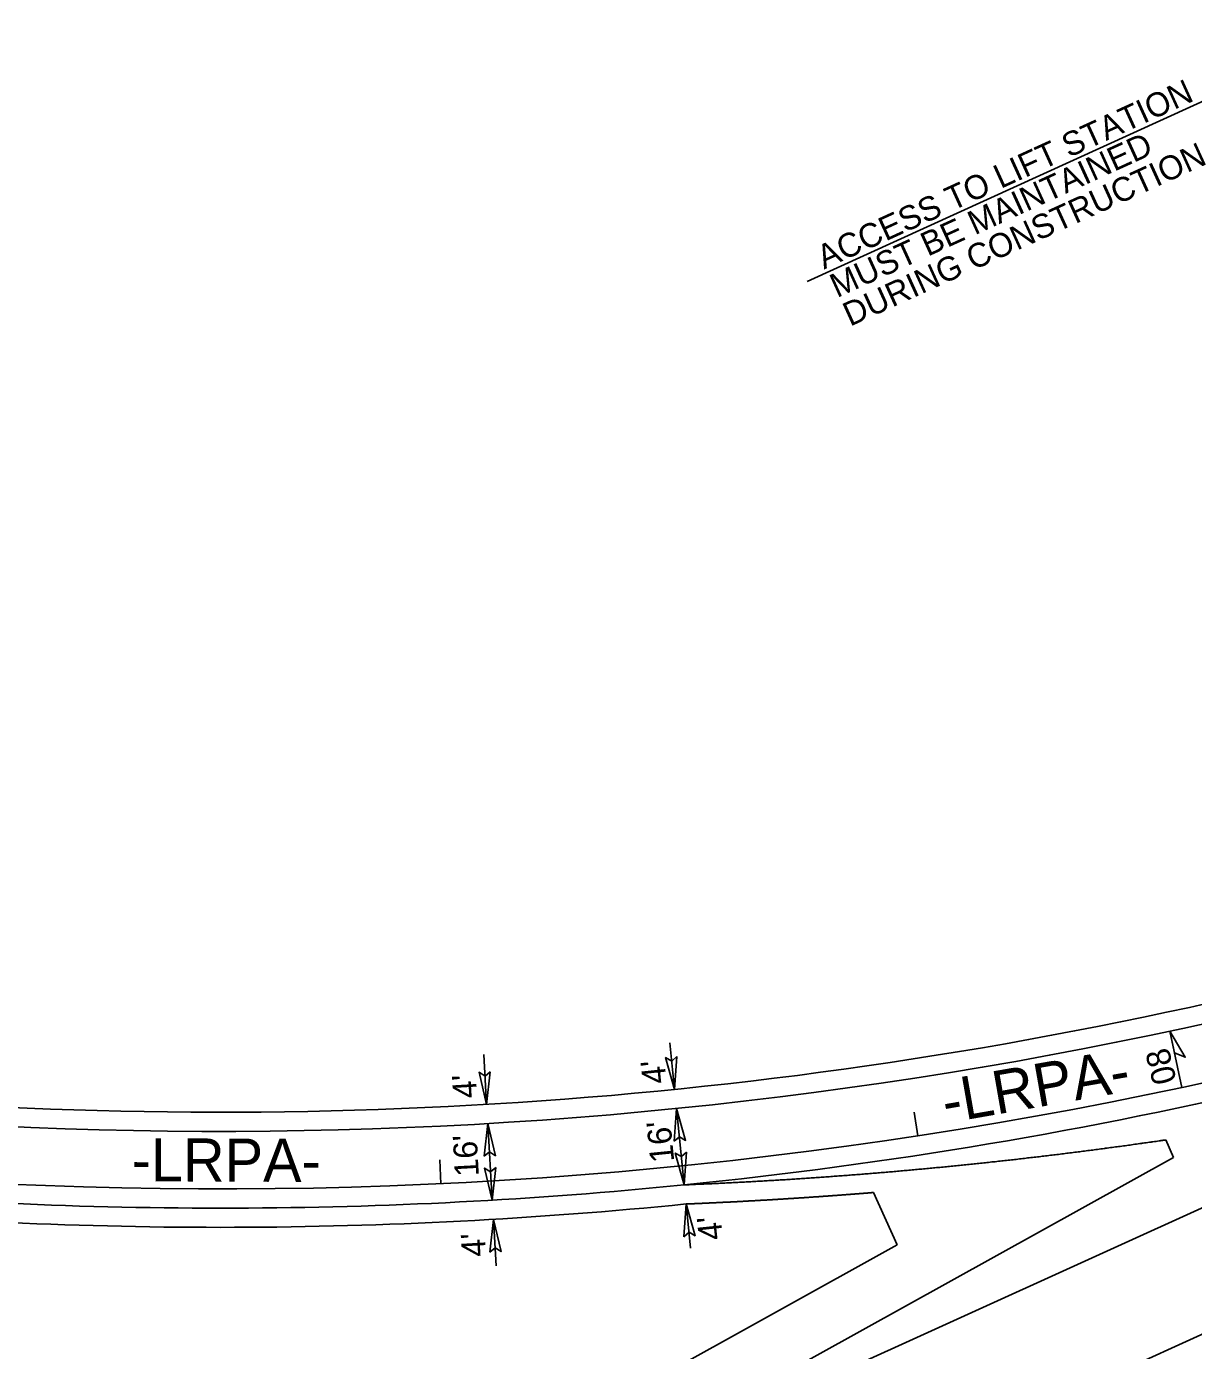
# Model space of a CAD drawing. Extents: x 2242984 to 2250974, y 661492 to 664681.
# Drawn here: x 2248196.5 to 2248439.9, y 663145.5 to 663421.5 of the extents above; entities that cross this region are included whole.
import ezdxf

# ---------------------------------------------------------------- set-up
doc = ezdxf.new("R2010")
doc.units = 0
for name, color, linetype in [('Prop Dimension', 7, 'Continuous'), ('Prop Dimension Text', 7, 'Continuous'), ('Prop DSN Text', 7, 'Continuous'), ('Prop EOT', 7, 'Continuous'), ('Prop Horizontal Alignment', 7, 'Continuous'), ('Prop Horizontal Alignment Curve and Spiral Data', 7, 'Continuous'), ('Prop Horizontal Alignment Tick Small', 7, 'Continuous'), ('Prop Lane Lines', 7, 'Continuous'), ('Prop Paved Shoulder', 7, 'Continuous'), ('Prop Superelevation  Arrow CELL', 7, 'Continuous'), ('Prop Superelevation Label', 7, 'Continuous'), ('Prop Terminator CELL', 7, 'Continuous'), ('Scratch_Level_2', 7, 'Continuous')]:
    doc.layers.add(name, color=color, linetype=linetype)

msp = doc.modelspace()

# ---------------------------------------------------------------- linework, layer by layer
at = {"layer": 'Prop Dimension'}
for p, q in [((2248330.69, 663209.61), (2248331.67, 663199.9)), ((2248292.46, 663196.78), (2248291.85, 663207.19)), ((2248332.07, 663195.92), (2248333.67, 663180)), ((2248293.64, 663176.81), (2248292.7, 663192.78)), ((2248335, 663166.83), (2248334.07, 663176.02)), ((2248294.45, 663163.1), (2248293.87, 663172.82))]:
    msp.add_line(p, q, dxfattribs=at)
at = {"layer": 'Prop DSN Text'}
msp.add_line((2248447.47, 663408.55), (2248359.33, 663368.39), dxfattribs=at)
at = {"layer": 'Prop EOT'}
for p, q in [((2248200.21, 663039.2), (2249433.89, 663599.6)), ((2248435.75, 663185.74), (2248434.1, 663189.38)), ((2248304.14, 663112.77), (2248435.75, 663185.74))]:
    msp.add_line(p, q, dxfattribs=at)
for radius, start, end in [(948, 264.58168, 292.13013), (964, 264.58443, 275.75472)]:
    msp.add_arc((2248237.01, 664139.15), radius, start, end, dxfattribs=at)
for points in [[(2248434.1, 663189.38), (2248433.42, 663189.28), (2248432.74, 663189.18), (2248432.07, 663189.08), (2248431.39, 663188.99), (2248430.71, 663188.89), (2248430.04, 663188.79), (2248429.36, 663188.7), (2248428.68, 663188.6), (2248428, 663188.51), (2248427.33, 663188.41), (2248426.65, 663188.32), (2248425.97, 663188.23), (2248425.3, 663188.13), (2248424.62, 663188.04), (2248423.94, 663187.95), (2248423.26, 663187.86), (2248422.59, 663187.77), (2248421.91, 663187.68), (2248421.23, 663187.58), (2248420.55, 663187.5), (2248419.88, 663187.41), (2248419.2, 663187.32), (2248418.52, 663187.23), (2248417.84, 663187.14), (2248417.17, 663187.05), (2248416.49, 663186.97), (2248415.81, 663186.88), (2248415.13, 663186.8), (2248414.46, 663186.71), (2248413.78, 663186.63), (2248413.1, 663186.54), (2248412.42, 663186.46), (2248411.74, 663186.37), (2248411.07, 663186.29), (2248410.39, 663186.21), (2248409.71, 663186.13), (2248409.03, 663186.05), (2248408.35, 663185.96), (2248407.68, 663185.88), (2248407, 663185.8), (2248406.32, 663185.72), (2248405.64, 663185.65), (2248404.96, 663185.57), (2248404.29, 663185.49), (2248403.61, 663185.41), (2248402.93, 663185.33), (2248402.25, 663185.26), (2248401.57, 663185.18), (2248400.89, 663185.11), (2248400.22, 663185.03), (2248399.54, 663184.96), (2248398.86, 663184.88), (2248398.18, 663184.81), (2248397.5, 663184.74), (2248396.82, 663184.66), (2248396.15, 663184.59), (2248395.47, 663184.52), (2248394.79, 663184.45), (2248394.11, 663184.38), (2248393.43, 663184.31), (2248392.75, 663184.24), (2248392.07, 663184.17), (2248391.4, 663184.1), (2248390.72, 663184.03), (2248390.04, 663183.96), (2248389.36, 663183.89), (2248388.68, 663183.83), (2248388, 663183.76), (2248387.32, 663183.69), (2248386.64, 663183.63), (2248385.97, 663183.56), (2248385.29, 663183.5), (2248384.61, 663183.44), (2248383.93, 663183.37)], [(2248383.93, 663183.37), (2248383.25, 663183.31), (2248382.57, 663183.25), (2248381.89, 663183.18), (2248381.21, 663183.12), (2248380.53, 663183.06), (2248379.86, 663183), (2248379.18, 663182.94), (2248378.5, 663182.88), (2248377.82, 663182.82), (2248377.14, 663182.76), (2248376.46, 663182.7), (2248375.78, 663182.65), (2248375.1, 663182.59), (2248374.42, 663182.53), (2248373.74, 663182.48), (2248373.06, 663182.42), (2248372.39, 663182.37), (2248371.71, 663182.31), (2248371.03, 663182.26), (2248370.35, 663182.2), (2248369.67, 663182.15), (2248368.99, 663182.1), (2248368.31, 663182.04), (2248367.63, 663181.99), (2248366.95, 663181.94), (2248366.27, 663181.89), (2248365.59, 663181.84), (2248364.92, 663181.79), (2248364.24, 663181.74), (2248363.56, 663181.69), (2248362.88, 663181.64), (2248362.2, 663181.59), (2248361.52, 663181.54), (2248360.84, 663181.5), (2248360.16, 663181.45), (2248359.48, 663181.4), (2248358.8, 663181.36), (2248358.12, 663181.31), (2248357.44, 663181.27), (2248356.76, 663181.22), (2248356.09, 663181.18), (2248355.41, 663181.14), (2248354.73, 663181.09), (2248354.05, 663181.05), (2248353.37, 663181.01), (2248352.69, 663180.97), (2248352.01, 663180.93), (2248351.33, 663180.89), (2248350.65, 663180.85), (2248349.97, 663180.81), (2248349.29, 663180.77), (2248348.61, 663180.73), (2248347.93, 663180.69), (2248347.26, 663180.65), (2248346.58, 663180.62), (2248345.9, 663180.58), (2248345.22, 663180.54), (2248344.54, 663180.51), (2248343.86, 663180.47), (2248343.18, 663180.44), (2248342.5, 663180.41), (2248341.82, 663180.37), (2248341.14, 663180.34), (2248340.46, 663180.31), (2248339.78, 663180.27), (2248339.1, 663180.24), (2248338.43, 663180.21), (2248337.75, 663180.18), (2248337.07, 663180.15), (2248336.39, 663180.12), (2248335.71, 663180.09), (2248335.03, 663180.06), (2248333.67, 663180)]]:
    msp.add_spline(points, degree=3, dxfattribs=at)
at = {"layer": 'Prop Horizontal Alignment'}
msp.add_arc((2248237.01, 664139.15), 960, 261.59641, 292.13013, dxfattribs=at)
at = {"layer": 'Prop Horizontal Alignment Tick Small'}
for p, q in [((2248382.4, 663190.22), (2248381.64, 663195.16)), ((2248282.94, 663180.25), (2248282.71, 663185.24))]:
    msp.add_line(p, q, dxfattribs=at)
at = {"layer": 'Prop Lane Lines'}
msp.add_line((2248304.14, 663112.77), (2248668.27, 663278.18), dxfattribs=at)
msp.add_arc((2248237.01, 664139.15), 964, 275.75472, 290.97015, dxfattribs=at)
at = {"layer": 'Prop Paved Shoulder'}
for p, q in [((2248378.08, 663167.49), (2248373.12, 663178.41)), ((2248298.74, 663123.5), (2248378.08, 663167.49))]:
    msp.add_line(p, q, dxfattribs=at)
for radius, start, end in [(944, 264.58097, 283.54456), (968, 264.58516, 275.75472)]:
    msp.add_arc((2248237.01, 664139.15), radius, start, end, dxfattribs=at)
msp.add_open_spline([(2248373.12, 663178.41), (2248372.98, 663178.4), (2248372.85, 663178.39), (2248372.71, 663178.38), (2248372.48, 663178.36), (2248372.26, 663178.34), (2248372.03, 663178.32), (2248371.8, 663178.3), (2248371.57, 663178.29), (2248371.35, 663178.27), (2248371.12, 663178.25), (2248370.89, 663178.23), (2248370.66, 663178.21), (2248370.44, 663178.2), (2248370.21, 663178.18), (2248369.98, 663178.16), (2248369.75, 663178.14), (2248369.53, 663178.13), (2248369.3, 663178.11), (2248369.07, 663178.09), (2248368.85, 663178.07), (2248368.62, 663178.05), (2248368.39, 663178.04), (2248368.16, 663178.02), (2248367.94, 663178), (2248367.71, 663177.99), (2248367.48, 663177.97), (2248367.25, 663177.95), (2248367.03, 663177.93), (2248366.8, 663177.92), (2248366.57, 663177.9), (2248366.34, 663177.88), (2248366.12, 663177.87), (2248365.89, 663177.85), (2248365.66, 663177.83), (2248365.44, 663177.82), (2248365.21, 663177.8), (2248364.98, 663177.78), (2248364.75, 663177.77), (2248364.53, 663177.75), (2248364.3, 663177.73), (2248364.07, 663177.72), (2248363.84, 663177.7), (2248363.62, 663177.68), (2248363.39, 663177.67), (2248363.16, 663177.65), (2248362.93, 663177.63), (2248362.71, 663177.62), (2248362.48, 663177.6), (2248362.25, 663177.59), (2248362.03, 663177.57), (2248361.8, 663177.55), (2248361.57, 663177.54), (2248361.34, 663177.52), (2248361.12, 663177.51), (2248360.89, 663177.49), (2248360.66, 663177.48), (2248360.43, 663177.46), (2248360.21, 663177.44), (2248359.98, 663177.43), (2248359.75, 663177.41), (2248359.52, 663177.4), (2248359.3, 663177.38), (2248359.07, 663177.37), (2248358.84, 663177.35), (2248358.62, 663177.34), (2248358.39, 663177.32), (2248358.16, 663177.31), (2248357.93, 663177.29), (2248357.71, 663177.28), (2248357.48, 663177.26), (2248357.25, 663177.25), (2248357.02, 663177.23), (2248356.8, 663177.22), (2248356.57, 663177.2), (2248356.34, 663177.19), (2248356.11, 663177.17), (2248355.89, 663177.16), (2248355.66, 663177.15), (2248355.43, 663177.13), (2248355.2, 663177.12), (2248354.98, 663177.1), (2248354.75, 663177.09), (2248354.52, 663177.07), (2248354.3, 663177.06), (2248354.07, 663177.05), (2248353.84, 663177.03), (2248353.61, 663177.02), (2248353.39, 663177), (2248353.16, 663176.99), (2248352.93, 663176.98), (2248352.7, 663176.96), (2248352.48, 663176.95), (2248352.25, 663176.93), (2248352.02, 663176.92), (2248351.79, 663176.91), (2248351.57, 663176.89), (2248351.34, 663176.88), (2248351.11, 663176.87), (2248350.89, 663176.85), (2248350.66, 663176.84), (2248350.43, 663176.83), (2248350.2, 663176.81), (2248349.98, 663176.8), (2248349.75, 663176.79), (2248349.52, 663176.78), (2248349.29, 663176.76), (2248349.07, 663176.75), (2248348.84, 663176.74), (2248348.61, 663176.72), (2248348.38, 663176.71), (2248348.16, 663176.7), (2248347.93, 663176.69), (2248347.7, 663176.67), (2248347.47, 663176.66), (2248347.25, 663176.65), (2248347.02, 663176.64), (2248346.79, 663176.62), (2248346.57, 663176.61), (2248346.34, 663176.6), (2248346.11, 663176.59), (2248345.88, 663176.57), (2248345.66, 663176.56), (2248345.43, 663176.55), (2248345.2, 663176.54), (2248344.97, 663176.53), (2248344.75, 663176.51), (2248344.52, 663176.5), (2248344.29, 663176.49), (2248344.06, 663176.48), (2248343.84, 663176.47), (2248343.61, 663176.46), (2248343.38, 663176.44), (2248343.15, 663176.43), (2248342.93, 663176.42), (2248342.7, 663176.41), (2248342.47, 663176.4), (2248342.25, 663176.39), (2248342.02, 663176.38), (2248341.79, 663176.37), (2248341.56, 663176.35), (2248341.34, 663176.34), (2248341.11, 663176.33), (2248340.88, 663176.32), (2248340.65, 663176.31), (2248340.43, 663176.3), (2248340.2, 663176.29), (2248339.97, 663176.28), (2248339.74, 663176.27), (2248339.52, 663176.26), (2248339.29, 663176.25), (2248339.06, 663176.24), (2248338.84, 663176.22), (2248338.61, 663176.21), (2248338.38, 663176.2), (2248338.15, 663176.19), (2248337.93, 663176.18), (2248337.7, 663176.17), (2248337.47, 663176.16), (2248337.24, 663176.15), (2248337.02, 663176.14), (2248336.79, 663176.13), (2248336.56, 663176.12), (2248336.33, 663176.11), (2248336.11, 663176.1), (2248335.88, 663176.09), (2248335.65, 663176.08), (2248335.42, 663176.07), (2248335.2, 663176.06), (2248334.74, 663176.05), (2248334.29, 663176.03), (2248334.07, 663176.02)], degree=3, dxfattribs=at)
at = {"layer": 'Prop Superelevation  Arrow CELL'}
msp.add_line((2248434.97, 663212.05), (2248437.48, 663200.31), dxfattribs=at)
msp.add_lwpolyline([(2248434.97, 663212.05), (2248438.18, 663206.6), (2248435.94, 663207.52)], close=True, dxfattribs=at)
at = {"layer": 'Prop Terminator CELL'}
for points in [[(2248332.15, 663206.74), (2248331.67, 663199.9), (2248329.79, 663206.54), (2248331.07, 663205.8)], [(2248293.23, 663203.58), (2248292.46, 663196.78), (2248290.87, 663203.48), (2248292.12, 663202.69)], [(2248331.59, 663189.09), (2248332.07, 663195.92), (2248333.94, 663189.29), (2248332.66, 663190.03)], [(2248291.94, 663185.98), (2248292.7, 663192.78), (2248294.3, 663186.08), (2248293.05, 663186.87)], [(2248334.15, 663186.84), (2248333.67, 663180), (2248331.8, 663186.64), (2248333.08, 663185.9)], [(2248294.4, 663183.62), (2248293.64, 663176.81), (2248292.04, 663183.52), (2248293.29, 663182.73)], [(2248333.59, 663169.19), (2248334.07, 663176.02), (2248335.95, 663169.39), (2248334.67, 663170.13)], [(2248293.11, 663166.01), (2248293.87, 663172.82), (2248295.47, 663166.11), (2248294.22, 663166.9)]]:
    msp.add_lwpolyline(points, close=True, dxfattribs=at)
at = {"layer": 'Scratch_Level_2'}
msp.add_line((2248298.74, 663123.5), (2248378.08, 663167.49), dxfattribs=at)

# ---------------------------------------------------------------- texts
at = {"layer": 'Prop Dimension Text'}
for s, rotation, p in [("4'", 95.9431, (2248330.02, 663201.3)), ("4'", 93.3677, (2248290.49, 663198.18)), ("16'", 95.7547, (2248331.61, 663184.9)), ("16'", 93.1442, (2248290.85, 663181.87)), ("4'", 95.9431, (2248341.75, 663168.73)), ("4'", 93.3677, (2248292.33, 663165.14))]:
    msp.add_text(s, height=5, rotation=rotation, dxfattribs=at).set_placement(p)
at = {"layer": 'Prop DSN Text'}
for s, p in [('ACCESS TO LIFT STATION', (2248362.83, 663370.85)), ('MUST BE MAINTAINED ', (2248365.54, 663364.89)), ('DURING CONSTRUCTION', (2248368.26, 663358.92))]:
    msp.add_text(s, height=5, rotation=24.4979, dxfattribs=at).set_placement(p)
at = {"layer": 'Prop Horizontal Alignment Curve and Spiral Data'}
for rotation, p in [(9.9526, (2248388.25, 663192.82)), (359.7584, (2248218.4, 663180.76))]:
    msp.add_text('-LRPA-', height=9, rotation=rotation, dxfattribs=at).set_placement(p)
at = {"layer": 'Prop Superelevation Label'}
msp.add_text('08', height=5, rotation=104.0129, dxfattribs=at).set_placement((2248436.42, 663201.66))

doc.saveas('drawing.dxf')
